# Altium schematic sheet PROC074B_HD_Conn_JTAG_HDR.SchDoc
size 431 x 279 mm; Date: Not shown in title block; ApprovedBy: Not shown in title block; CheckedBy: Not shown in title block; Author: Not shown in title block; CompanyName: Not shown in title block; Engineer: Not shown in title block; Organization: Not shown in title block; Address1: Not shown in title block; Address2: Not shown in title block; Address3: Not shown in title block; Address4: Not shown in title block; DocumentNumber: 1; Revision: Use project parameter SCH_Rev; SheetNumber: 10; SheetTotal: 22; PageSetup: Record=PageOptions¦CenterHorizontal=True¦CenterVertical=True¦PrintScale=1.00¦XCorrection=1.00¦YCorrection=1.00¦PrintKind=0¦BorderSize=5000000¦LeftOffset=0¦BottomOffset=0¦Orientation=2¦PaperLength=1000¦PaperWidth=1000¦Scale=100¦PaperSource=15¦PrintQuality=600¦MediaType=1¦DitherType=10¦PaperKind=Letter¦PrintScaleMode=1
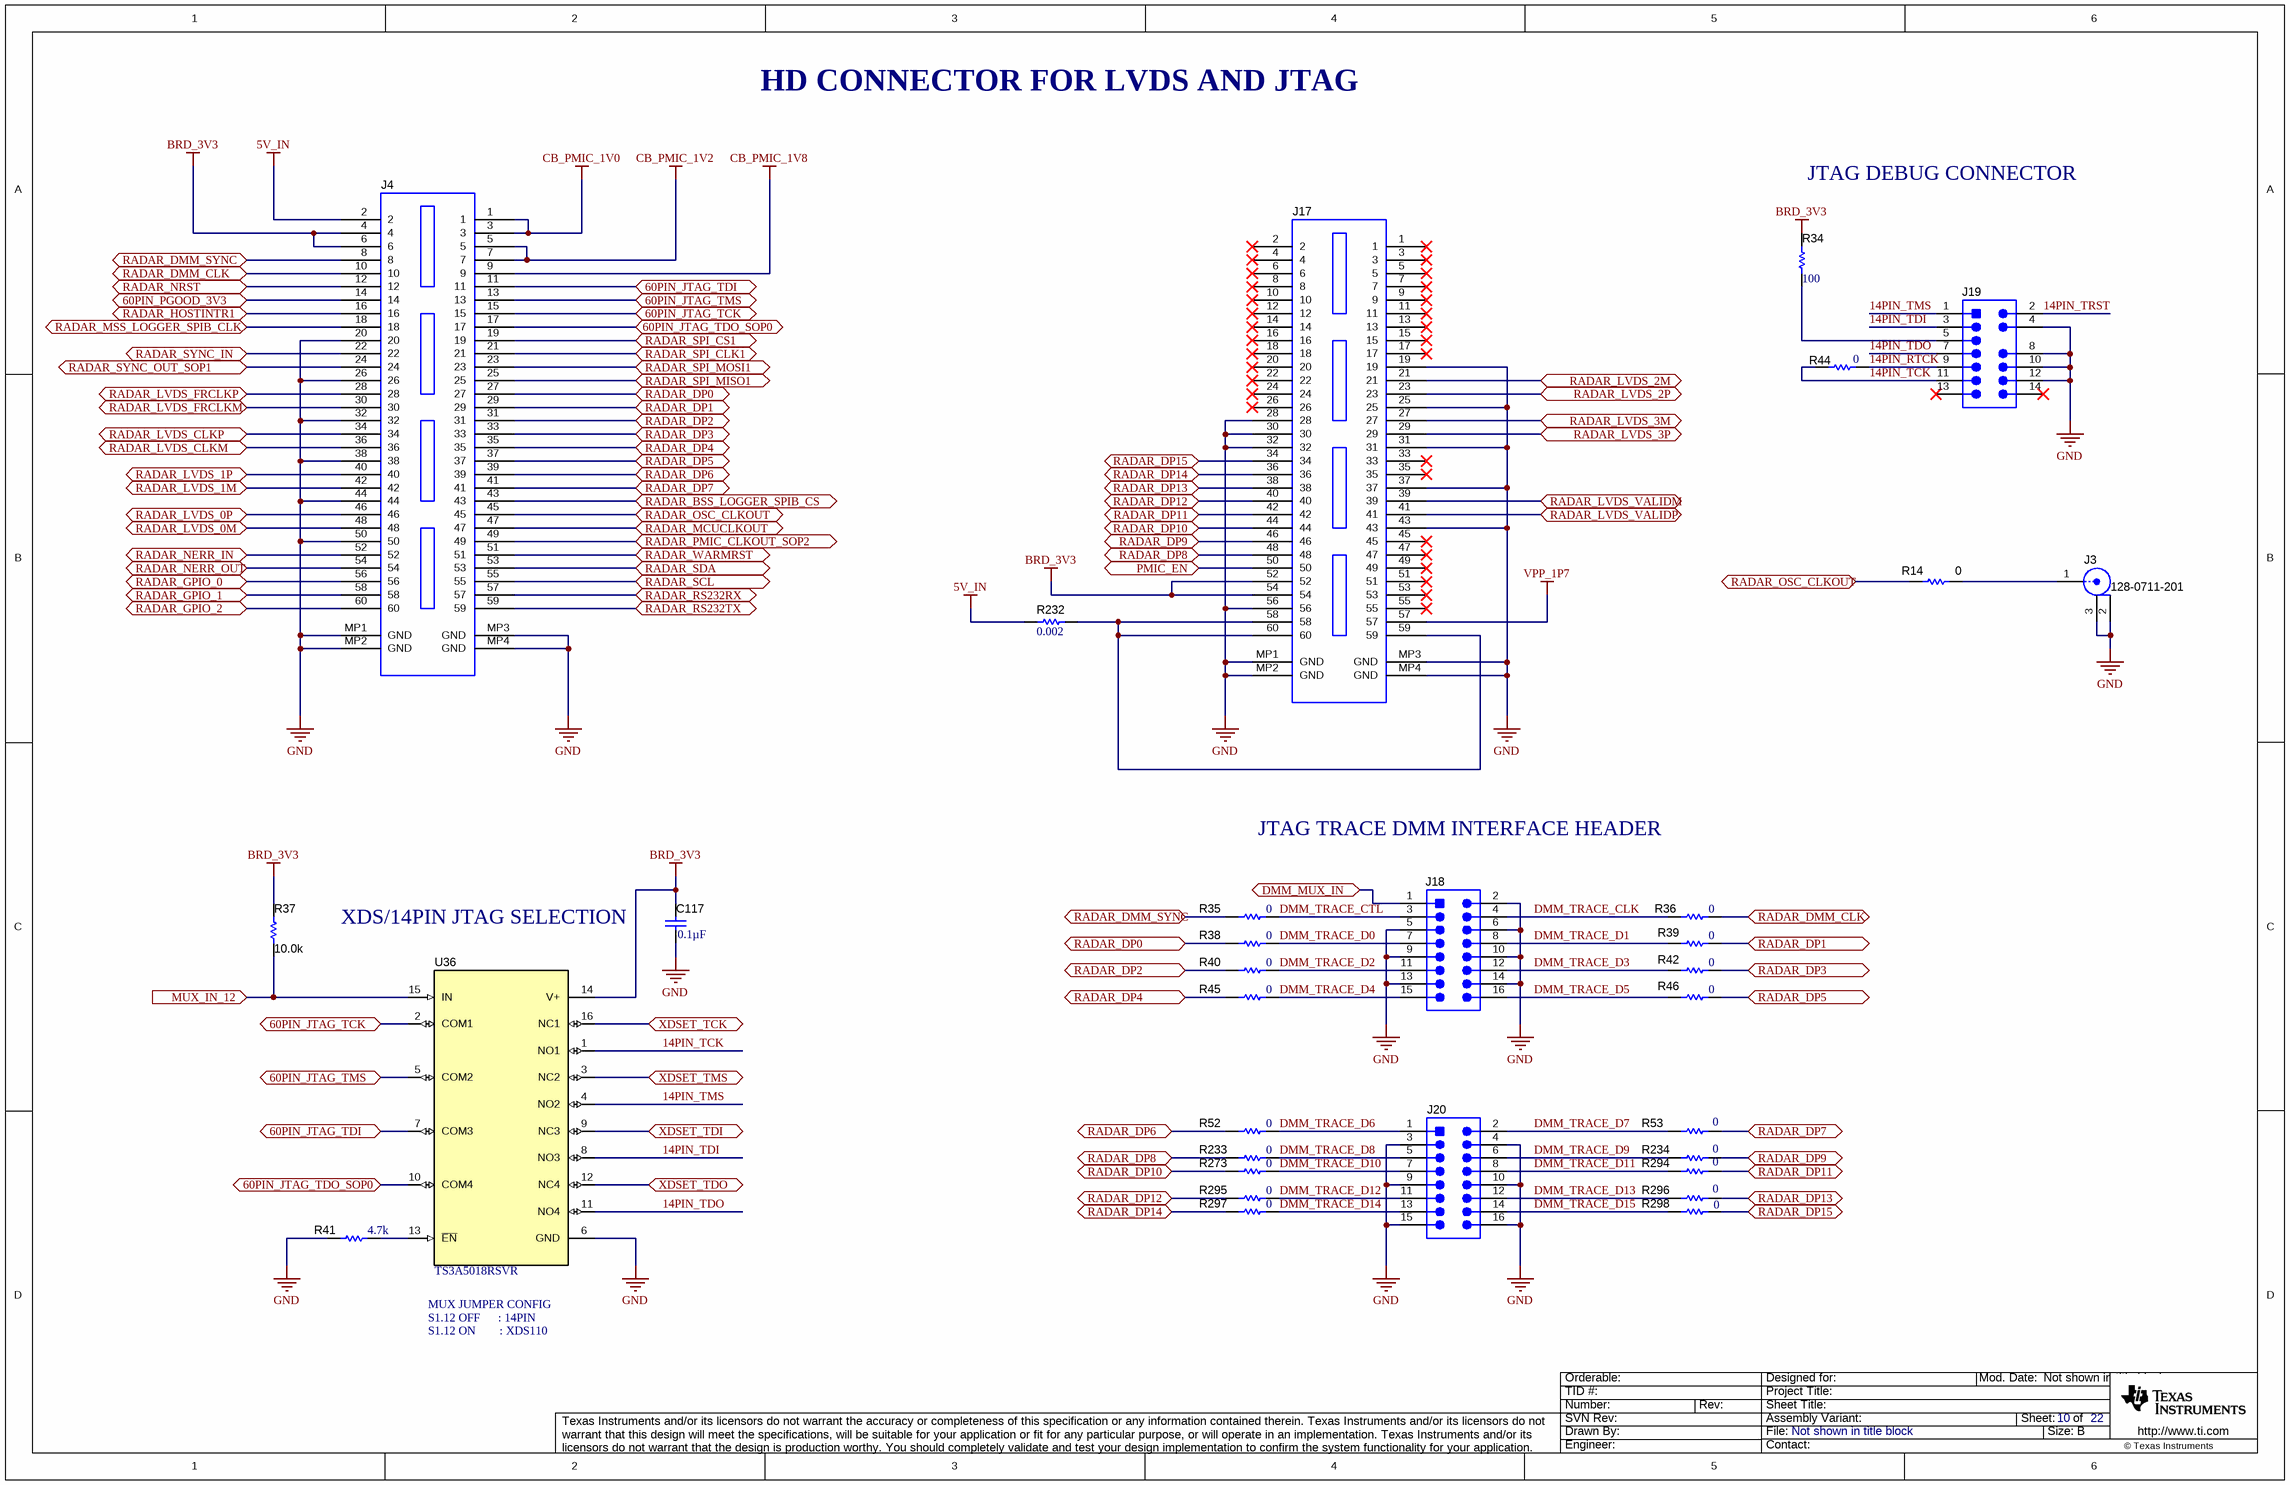
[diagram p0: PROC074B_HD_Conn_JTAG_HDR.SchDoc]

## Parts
C117  ValueDisplayed: 0.1µF  [0402]  (hidden comment: C0402C104K8RACTU)
J3  128-0711-201  [Johnson_128-0711-201]
J4  QTH-030-01-L-D-A  [Samtec_QTH-030-01-x-D-A]  (value not drawn)
J17  QTH-030-01-L-D-A  [Samtec_QTH-030-01-x-D-A]  (value not drawn)
J18  TSW-108-07-G-D  [TSW-108-07-G-D]  (value not drawn)
J19  TSW-107-07-L-D-006  [Samtec_TSW-107-07-L-D-006]  (value not drawn)
J20  TSW-108-07-G-D  [TSW-108-07-G-D]  (value not drawn)
R14  ValueDisplayed: 0  [0201_Silk]  (hidden comment: CRCW02010000Z0ED)
R34  ValueDisplayed: 100  [0402]  (hidden comment: ERJ-2GEJ101X)
R35  ValueDisplayed: 0  [0402]  (hidden comment: ERJ-2GE0R00X)
R36  ValueDisplayed: 0  [0402]  (hidden comment: ERJ-2GE0R00X)
R37  ValueDisplayed: 10.0k  [0402L]  (hidden comment: CRCW040210K0FKED)
R38  ValueDisplayed: 0  [0402]  (hidden comment: ERJ-2GE0R00X)
R39  ValueDisplayed: 0  [0402]  (hidden comment: ERJ-2GE0R00X)
R40  ValueDisplayed: 0  [0402]  (hidden comment: ERJ-2GE0R00X)
R41  ValueDisplayed: 4.7k  [0402]  (hidden comment: CRCW04024K70JNED)
R42  ValueDisplayed: 0  [0402]  (hidden comment: ERJ-2GE0R00X)
R44  ValueDisplayed: 0  [0402]  (hidden comment: ERJ-2GE0R00X)
R45  ValueDisplayed: 0  [0402]  (hidden comment: ERJ-2GE0R00X)
R46  ValueDisplayed: 0  [0402]  (hidden comment: ERJ-2GE0R00X)
R52  ValueDisplayed: 0  [0402]  (hidden comment: ERJ-2GE0R00X)
R53  ValueDisplayed: 0  [0402]  (hidden comment: ERJ-2GE0R00X)
R232  ValueDisplayed: 0.002  [1206]  (hidden comment: PMR18EZPFV2L00)
R233  ValueDisplayed: 0  [0402]  (hidden comment: ERJ-2GE0R00X)
R234  ValueDisplayed: 0  [0402]  (hidden comment: ERJ-2GE0R00X)
R273  ValueDisplayed: 0  [0402]  (hidden comment: ERJ-2GE0R00X)
R294  ValueDisplayed: 0  [0402]  (hidden comment: ERJ-2GE0R00X)
R295  ValueDisplayed: 0  [0402]  (hidden comment: ERJ-2GE0R00X)
R296  ValueDisplayed: 0  [0402]  (hidden comment: ERJ-2GE0R00X)
R297  ValueDisplayed: 0  [0402]  (hidden comment: ERJ-2GE0R00X)
R298  ValueDisplayed: 0  [0402]  (hidden comment: ERJ-2GE0R00X)
U36  TS3A5018RSVR  [RSV0016A]

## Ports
60PIN_JTAG_TCK, 60PIN_JTAG_TDI, 60PIN_JTAG_TDO_SOP0, 60PIN_JTAG_TMS, 60PIN_PGOOD_3V3, DMM_MUX_IN, MUX_IN_12 (in), PMIC_EN, RADAR_BSS_LOGGER_SPIB_CS, RADAR_DMM_CLK, RADAR_DMM_SYNC, RADAR_DP0, RADAR_DP1, RADAR_DP2, RADAR_DP3, RADAR_DP4, RADAR_DP5, RADAR_DP6, RADAR_DP7, RADAR_DP8, RADAR_DP9, RADAR_DP10, RADAR_DP11, RADAR_DP12, RADAR_DP13, RADAR_DP14, RADAR_DP15, RADAR_GPIO_0, RADAR_GPIO_1, RADAR_GPIO_2, RADAR_HOSTINTR1, RADAR_LVDS_0M, RADAR_LVDS_0P, RADAR_LVDS_1M, RADAR_LVDS_1P, RADAR_LVDS_2M, RADAR_LVDS_2P, RADAR_LVDS_3M, RADAR_LVDS_3P, RADAR_LVDS_CLKM, RADAR_LVDS_CLKP, RADAR_LVDS_FRCLKM, RADAR_LVDS_FRCLKP, RADAR_LVDS_VALIDM, RADAR_LVDS_VALIDP, RADAR_MCUCLKOUT, RADAR_MSS_LOGGER_SPIB_CLK, RADAR_NERR_IN, RADAR_NERR_OUT, RADAR_NRST, RADAR_OSC_CLKOUT, RADAR_PMIC_CLKOUT_SOP2, RADAR_RS232RX, RADAR_RS232TX, RADAR_SCL, RADAR_SDA, RADAR_SPI_CLK1, RADAR_SPI_CS1, RADAR_SPI_MISO1, RADAR_SPI_MOSI1, RADAR_SYNC_IN, RADAR_SYNC_OUT_SOP1, RADAR_WARMRST, XDSET_TCK, XDSET_TDI, XDSET_TDO, XDSET_TMS

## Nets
5V_IN: J4.2 R232.2
BRD_3V3: C117.1 J4.4 J4.6 J17.52 J17.54 R34.2 R37.2 U36.14(V+)
CB_PMIC_1V0: J4.1 J4.3
CB_PMIC_1V2: J4.5 J4.7
CB_PMIC_1V8: J4.9
GND: C117.2 J3.2 J3.3 J4.20 J4.26 J4.32 J4.38 J4.44 J4.50 J4.MP1(GND) J4.MP2(GND) J4.MP3(GND) J4.MP4(GND) J17.19 J17.25 J17.28 J17.30 J17.31 J17.32 J17.37 J17.43 J17.56 J17.MP1(GND) J17.MP2(GND) J17.MP3(GND) J17.MP4(GND) J18.2 J18.5 J18.6 J18.9 J18.10 J18.13 J18.14 J19.4 J19.8 J19.10 J19.12 J20.3 J20.4 J20.9 J20.10 J20.15 J20.16 R41.1 U36.6(GND)
VPP_1P7: J17.57
14PIN_RTCK: J19.9 R44.2
14PIN_TCK: J19.11 R44.1 U36.1(NO1)
14PIN_TDI: J19.3 U36.8(NO3)
14PIN_TDO: J19.7 U36.11(NO4)
14PIN_TMS: J19.1 U36.4(NO2)
14PIN_TRST: J19.2
60PIN_JTAG_TCK: J4.15 U36.2(COM1) ; port 60PIN_JTAG_TCK
60PIN_JTAG_TDI: J4.11 U36.7(COM3) ; port 60PIN_JTAG_TDI
60PIN_JTAG_TDO_SOP0: J4.17 U36.10(COM4) ; port 60PIN_JTAG_TDO_SOP0
60PIN_JTAG_TMS: J4.13 U36.5(COM2) ; port 60PIN_JTAG_TMS
60PIN_PGOOD_3V3: J4.14 ; port 60PIN_PGOOD_3V3
DMM_MUX_IN: J18.1 ; port DMM_MUX_IN
DMM_TRACE_CLK: J18.4 R36.1
DMM_TRACE_CTL: J18.3 R35.2
DMM_TRACE_D0: J18.7 R38.2
DMM_TRACE_D1: J18.8 R39.1
DMM_TRACE_D2: J18.11 R40.2
DMM_TRACE_D3: J18.12 R42.1
DMM_TRACE_D4: J18.15 R45.2
DMM_TRACE_D5: J18.16 R46.1
DMM_TRACE_D6: J20.1 R52.2
DMM_TRACE_D7: J20.2 R53.1
DMM_TRACE_D8: J20.5 R233.2
DMM_TRACE_D9: J20.6 R234.1
DMM_TRACE_D10: J20.7 R273.2
DMM_TRACE_D11: J20.8 R294.1
DMM_TRACE_D12: J20.11 R295.2
DMM_TRACE_D13: J20.12 R296.1
DMM_TRACE_D14: J20.13 R297.2
DMM_TRACE_D15: J20.14 R298.1
MUX_IN_12: R37.1 U36.15(IN) ; port MUX_IN_12
PMIC_EN: J17.50 ; port PMIC_EN
RADAR_BSS_LOGGER_SPIB_CS: J4.43 ; port RADAR_BSS_LOGGER_SPIB_CS
RADAR_DMM_CLK: J4.10 R36.2 ; port RADAR_DMM_CLK
RADAR_DMM_SYNC: J4.8 R35.1 ; port RADAR_DMM_SYNC
RADAR_DP0: J4.27 R38.1 ; port RADAR_DP0
RADAR_DP1: J4.29 R39.2 ; port RADAR_DP1
RADAR_DP2: J4.31 R40.1 ; port RADAR_DP2
RADAR_DP3: J4.33 R42.2 ; port RADAR_DP3
RADAR_DP4: J4.35 R45.1 ; port RADAR_DP4
RADAR_DP5: J4.37 R46.2 ; port RADAR_DP5
RADAR_DP6: J4.39 R52.1 ; port RADAR_DP6
RADAR_DP7: J4.41 R53.2 ; port RADAR_DP7
RADAR_DP8: J17.48 R233.1 ; port RADAR_DP8
RADAR_DP9: J17.46 R234.2 ; port RADAR_DP9
RADAR_DP10: J17.44 R273.1 ; port RADAR_DP10
RADAR_DP11: J17.42 R294.2 ; port RADAR_DP11
RADAR_DP12: J17.40 R295.1 ; port RADAR_DP12
RADAR_DP13: J17.38 R296.2 ; port RADAR_DP13
RADAR_DP14: J17.36 R297.1 ; port RADAR_DP14
RADAR_DP15: J17.34 R298.2 ; port RADAR_DP15
RADAR_GPIO_0: J4.56 ; port RADAR_GPIO_0
RADAR_GPIO_1: J4.58 ; port RADAR_GPIO_1
RADAR_GPIO_2: J4.60 ; port RADAR_GPIO_2
RADAR_HOSTINTR1: J4.16 ; port RADAR_HOSTINTR1
RADAR_LVDS_0M: J4.48 ; port RADAR_LVDS_0M
RADAR_LVDS_0P: J4.46 ; port RADAR_LVDS_0P
RADAR_LVDS_1M: J4.42 ; port RADAR_LVDS_1M
RADAR_LVDS_1P: J4.40 ; port RADAR_LVDS_1P
RADAR_LVDS_2M: J17.21 ; port RADAR_LVDS_2M
RADAR_LVDS_2P: J17.23 ; port RADAR_LVDS_2P
RADAR_LVDS_3M: J17.27 ; port RADAR_LVDS_3M
RADAR_LVDS_3P: J17.29 ; port RADAR_LVDS_3P
RADAR_LVDS_CLKM: J4.36 ; port RADAR_LVDS_CLKM
RADAR_LVDS_CLKP: J4.34 ; port RADAR_LVDS_CLKP
RADAR_LVDS_FRCLKM: J4.30 ; port RADAR_LVDS_FRCLKM
RADAR_LVDS_FRCLKP: J4.28 ; port RADAR_LVDS_FRCLKP
RADAR_LVDS_VALIDM: J17.39 ; port RADAR_LVDS_VALIDM
RADAR_LVDS_VALIDP: J17.41 ; port RADAR_LVDS_VALIDP
RADAR_MCUCLKOUT: J4.47 ; port RADAR_MCUCLKOUT
RADAR_MSS_LOGGER_SPIB_CLK: J4.18 ; port RADAR_MSS_LOGGER_SPIB_CLK
RADAR_NERR_IN: J4.52 ; port RADAR_NERR_IN
RADAR_NERR_OUT: J4.54 ; port RADAR_NERR_OUT
RADAR_NRST: J4.12 ; port RADAR_NRST
RADAR_OSC_CLKOUT: J4.45 R14.1 ; port RADAR_OSC_CLKOUT
RADAR_PMIC_CLKOUT_SOP2: J4.49 ; port RADAR_PMIC_CLKOUT_SOP2
RADAR_RS232RX: J4.57 ; port RADAR_RS232RX
RADAR_RS232TX: J4.59 ; port RADAR_RS232TX
RADAR_SCL: J4.55 ; port RADAR_SCL
RADAR_SDA: J4.53 ; port RADAR_SDA
RADAR_SPI_CLK1: J4.21 ; port RADAR_SPI_CLK1
RADAR_SPI_CS1: J4.19 ; port RADAR_SPI_CS1
RADAR_SPI_MISO1: J4.25 ; port RADAR_SPI_MISO1
RADAR_SPI_MOSI1: J4.23 ; port RADAR_SPI_MOSI1
RADAR_SYNC_IN: J4.22 ; port RADAR_SYNC_IN
RADAR_SYNC_OUT_SOP1: J4.24 ; port RADAR_SYNC_OUT_SOP1
RADAR_WARMRST: J4.51 ; port RADAR_WARMRST
XDSET_TCK: U36.16(NC1) ; port XDSET_TCK
XDSET_TDI: U36.9(NC3) ; port XDSET_TDI
XDSET_TDO: U36.12(NC4) ; port XDSET_TDO
XDSET_TMS: U36.3(NC2) ; port XDSET_TMS
NetJ3_1: J3.1 R14.2
NetJ17_58: J17.58 J17.59 J17.60 R232.1
NetJ19_5: J19.5 R34.1
NetR41_2: R41.2 U36.13(~{EN})

Not connected (* = marked no-connect by the designer): J17 1* 2* 3* 4* 5* 6* 7* 8* 9* 10* 11* 12* 13* 14* 15* 16* 17* 18* 20* 22* 24* 26* 33* 35* 45* 47* 49* 51* 53* 55*; J19 13* 14*

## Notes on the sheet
- HD CONNECTOR FOR LVDS AND JTAG
- JTAG DEBUG CONNECTOR
- JTAG TRACE DMM INTERFACE HEADER
- XDS/14PIN JTAG SELECTION
- MUX JUMPER CONFIG
- S1.12 OFF      : 14PIN
- S1.12 ON        : XDS110

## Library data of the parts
C117 = CMP-0078241-1: CAP, CERM, 0.1 µF, 10 V,+/- 10%, X7R, 0402; Manufacturer: Kemet; TaMin_C: -55°C; Polarized: N; SizeAreaWB_mm2: 3; U/M: EA; Value: 0.1uF; TaMax_C: 125°C; SizeZ_mm: 0.6; SizeX_mm: 1; SizeY_mm: 0.5; Value2: 10V; CompType: Capacitor; Cap_F: 100nF; AEC Category: Q200
J3 = CMP-0055788-1: UMC Straight Jack Receptacle, 50 Ohm, Gold, SMT; Manufacturer: Cinch Connectivity; CNHeader: FALSE; Gender: Female
J4 J17 = CMP-0075558-2: Header(Shrouded), 19.7mil, 30x2, Gold, SMT; Manufacturer: Samtec; Pitch_mm: 0.5; Gender: Male; Green_REACh: Passed; CT: False; Shrouded: Y; Green_Lifecycle: Active; Row_Count: 2
J18 J20 = CMP-0075418-1: Header, 100mil, 8x2, Gold, TH; Manufacturer: Samtec; Pitch_mm: 2.54; Cert_VDE: N; Gender: Male; Cert_CSA: Y; Voltage_V: 550V; Green_REACh: Passed; Current_A: 6.3A; CT: False; Green_Lifecycle: Active; Row_Count: 2; CNHeader: True
J19 = CMP-0081507-3: Header, 2.54mm, 13Pos, Gold with Tin tail, TH; Manufacturer: Samtec; Cert_UL: Y; Gender: Male; Pitch_mm: 2.54; Row_Count: 2; Shrouded: N
R14 = CMP-0027008-3: RES, 0, 5%, 0.05 W, 0201; Manufacturer: Vishay-Dale; Power_W: 50mW; TempCo: ppm/C; Value_Code: 0000; U/M: EA; Value: 0; EIA_Code: E24; SizeX_mm: 0.6; SizeY_mm: 0.3; SizeZ_mm: 0.26; Value2: 0.05W; SizeArea_mm2: 0.18; AEC Qualified: N; AEC Category: Q200
R34 = CMP-0026993-2: RES, 100, 5%, 0.1 W, AEC-Q200 Grade 0, 0402; Manufacturer: Panasonic; Power_W: 100mW; TempCo: 200 ppm/C; Value_Code: 100R; U/M: EA; Value: 100; EIA_Code: E24; SizeX_mm: 1; SizeY_mm: 0.5; SizeZ_mm: 0.6; Value2: 0.1W; AEC Qualified: Y; AEC Grade: 0; AEC Category: Q200
R35 R36 R38-R40 R42 R45 R46 R52 R53 R233 R234 R273 R294-R298 = CMP-0026992-3: RES, 0, 5%, 0.1 W, AEC-Q200 Grade 0, 0402; Manufacturer: Panasonic; Power_W: 100mW; TempCo: 600 ppm/C; Value_Code: 0000; Value: 0; EIA_Code: E24; SizeX_mm: 1; SizeY_mm: 0.5; SizeZ_mm: 0.6; Value2: 0.1W; CompType: Resistor; AEC Qualified: Y; VDC_V: 50V; AEC Category: Q200; SizeAreaWB_mm2: 3; INSTALLATION: DNP
R37 = CMP-0025958-2: RES, 10.0 k, 1%, 0.063 W, 0402; Manufacturer: Vishay-Dale; Power_W: 63mW; TempCo: 100 ppm/C; Value_Code: 10k0; U/M: EA; Value: 10.0k; EIA_Code: E96; Res_ohm: 10k; SizeX_mm: 1; SizeY_mm: 0.5; SizeZ_mm: 0.6; Value2: 0.063W; VDC_V: 50V; AEC Category: Q200
R41 = CMP-0026938-5: RES, 4.7 k, 5%, 0.063 W, AEC-Q200 Grade 0, 0402; Manufacturer: Vishay-Dale; Power_W: 63mW; TempCo: 200 ppm/C; Value_Code: 4k70; Value: 4.7k; EIA_Code: E24; SizeX_mm: 1; SizeY_mm: 0.5; SizeZ_mm: 0.6; Value2: 0.063W; AEC Qualified: Y; VDC_V: 50V; AEC Category: Q200; AEC Grade: 0
R44 = CMP-0026992-3: RES, 0, 5%, 0.1 W, AEC-Q200 Grade 0, 0402; Manufacturer: Panasonic; Power_W: 100mW; TempCo: 600 ppm/C; Value_Code: 0000; Value: 0; EIA_Code: E24; SizeX_mm: 1; SizeY_mm: 0.5; SizeZ_mm: 0.6; Value2: 0.1W; AEC Qualified: Y; VDC_V: 50V; AEC Category: Q200; SizeAreaWB_mm2: 3
R232 = CMP-0081623-1: RES, 0.002, 1%, 1 W, AEC-Q200 Grade 0, 1206; Manufacturer: Rohm; Value_Code: 2L000; SizeAreaWB_mm2: 10.92; SizeArea_mm2: 5.12; AEC Qualified: Y; AEC Category: Q200; Res_ohm: 2m; Value: 0.002; SizeZ_mm: 1.35; Green_REACh: Incomplete; TempCo: 100 ppm/C; AEC Grade: 0; Power_W: 1W; SizeY_mm: 1.6; Green_Lifecycle: Active; CompType: Resistor; SizeX_mm: 3.2; INSTALLATION: DNP
U36 = CMP-0067415-1: 10-Ohm Quad SPDT Analog Switch, RSV0016A (UQFN-16); Alternate Manufacturer: Texas Instruments; SizeAreaWB_mm2: 10.08; U/M: EA; SizeZ_mm: 0.55; SizeX_mm: 1.8; SizeY_mm: 2.6; SizeArea_mm2: 4.68; CompType: IC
